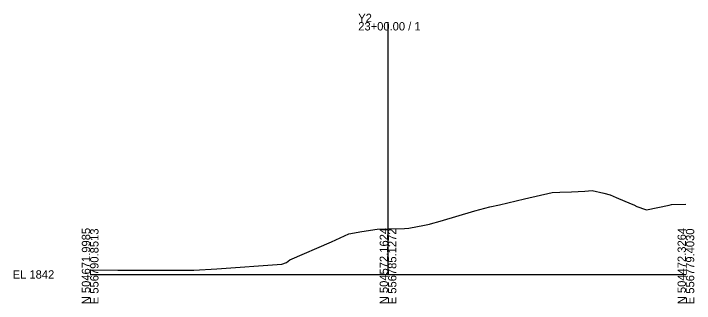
# Model space of a CAD drawing. Extents: x -26 to 203, y -10 to 3574.
# Drawn here: x -25.7 to 202.8, y 2990.3 to 3087.4 of the extents above; entities that cross this region are included whole.
import ezdxf

# ---------------------------------------------------------------- set-up
doc = ezdxf.new("R2010")
doc.units = 0
doc.layers.add('Exist Cross Section Cell', color=7, linetype='Continuous')
doc.layers.add('Exist XS Ground Line', color=7, linetype='Continuous')

msp = doc.modelspace()

# ---------------------------------------------------------------- linework, layer by layer
at = {"layer": 'Exist Cross Section Cell'}
for p, q in [((100, 3000), (100, 3084.58)), ((0, 3000), (100, 3000)), ((100, 3000), (200, 3000))]:
    msp.add_line(p, q, dxfattribs=at)
at = {"layer": 'Exist XS Ground Line'}
for p, q in [((166.06, 3027.96), (168.48, 3028.19)), ((168.48, 3028.19), (172.42, 3027.2)), ((145.77, 3025.39), (155.14, 3027.46)), ((155.14, 3027.46), (157.72, 3027.62)), ((157.72, 3027.62), (161.56, 3027.74)), ((161.56, 3027.74), (166.06, 3027.96)), ((172.42, 3027.2), (174.55, 3026.66)), ((174.55, 3026.66), (176.53, 3025.81)), ((176.53, 3025.81), (181.61, 3023.65)), ((137.41, 3023.34), (145.77, 3025.39)), ((181.61, 3023.65), (182.48, 3023.34)), ((195.17, 3023.41), (200, 3023.6)), ((117.51, 3017.9), (129.16, 3021.35)), ((129.16, 3021.35), (134.17, 3022.65)), ((134.17, 3022.65), (137.41, 3023.34)), ((182.48, 3023.34), (183.56, 3022.82)), ((183.56, 3022.82), (186.44, 3021.77)), ((186.44, 3021.77), (186.82, 3021.65)), ((186.82, 3021.65), (194.33, 3023.22)), ((194.33, 3023.22), (195.17, 3023.41)), ((112.29, 3016.57), (113.9, 3016.88)), ((113.9, 3016.88), (114.23, 3016.97)), ((114.23, 3016.97), (117.51, 3017.9)), ((86.84, 3013.6), (91.23, 3014.36)), ((91.23, 3014.36), (96.31, 3015.19)), ((96.31, 3015.19), (100, 3015.29)), ((100, 3015.29), (105.57, 3015.42)), ((105.57, 3015.42), (106.93, 3015.5)), ((106.93, 3015.5), (112.29, 3016.57)), ((81.01, 3010.97), (86.84, 3013.6)), ((67.08, 3004.87), (81.01, 3010.97)), ((42.51, 3001.89), (64.36, 3003.42)), ((64.36, 3003.42), (65.95, 3003.97)), ((65.95, 3003.97), (67.08, 3004.87)), ((0, 3001.58), (9.32, 3001.42)), ((9.32, 3001.42), (24.77, 3001.45)), ((24.77, 3001.45), (34.79, 3001.46)), ((34.79, 3001.46), (42.51, 3001.89))]:
    msp.add_line(p, q, dxfattribs=at)

# ---------------------------------------------------------------- texts
at = {"layer": 'Exist Cross Section Cell'}
for s, p in [('Y2', (90, 3084.58)), ('23+00.00 / 1', (90, 3081.78)), ('EL 1842', (-26, 2998.6))]:
    msp.add_text(s, height=2.8, dxfattribs=at).set_placement(p)
for s, p in [('N 504671.9985', (0, 2990)), ('E 556790.8513', (2.8, 2990)), ('N 504572.1624', (100, 2990)), ('E 556785.1272', (102.8, 2990)), ('N 504472.3264', (200, 2990)), ('E 556779.4030', (202.8, 2990))]:
    msp.add_text(s, height=2.8, rotation=90, dxfattribs=at).set_placement(p)

doc.saveas('drawing.dxf')
